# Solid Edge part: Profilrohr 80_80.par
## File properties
Username: ahadarics
Dokumentum tartalom típus: 0
Author: ahadarics
Last saved by: ahadarics
Revision: 80
Sűrűség: 0,000 kg/m^3
Pontosság: 0,990
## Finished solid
Body 1: solid body, 147 faces, 435 edges, 290 vertices.
  Faces by surface: cylinder 85, plane 62
  Edges by curve: line 265, circle 170
Bounding box of the edges (mm): 86.600 x 86.600 x 128.000, from (-43.3, -43.3, -91.5) to (43.3, 43.3, 36.5).
Cylindrical faces by radius (mm): R0.1 x8, R0.2 x30, R0.5 x22, R1 x8, R4.6 x4, R7 x4, R40 x1, R42.7 x8
Planar faces by outward normal: +x 6, +y 6, +z 1, -x 4, -y 4, -z 1, oblique 40
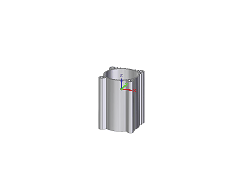
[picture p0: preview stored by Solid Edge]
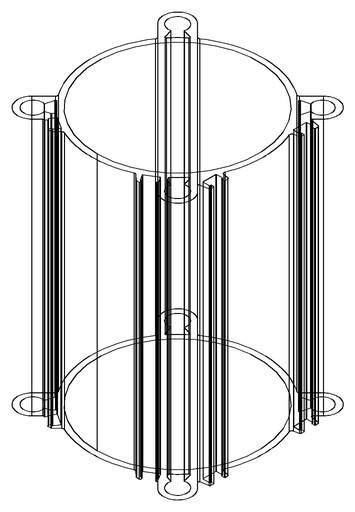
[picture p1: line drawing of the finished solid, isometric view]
